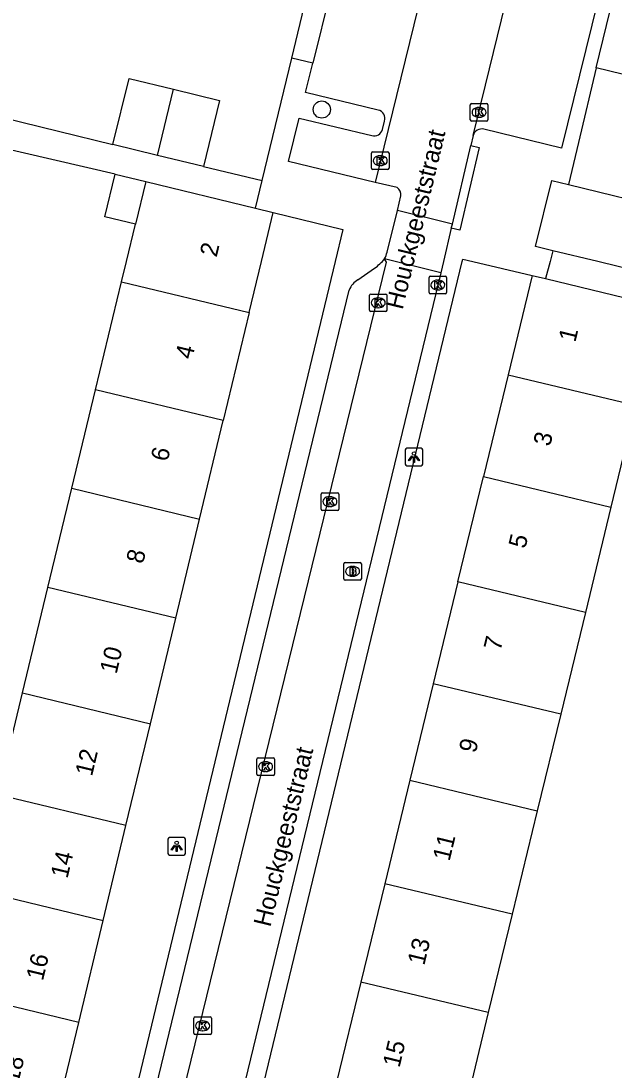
# Model space of a CAD drawing. Extents: x 162812 to 163818, y 381639 to 382470.
# Drawn here: x 163366.7 to 163400.4, y 382204.1 to 382263.7 of the extents above; entities that cross this region are included whole.
import ezdxf

# ---------------------------------------------------------------- set-up
doc = ezdxf.new("R2010")
doc.units = 0
for name, color, linetype in [('IMGEO_Boom', 7, 'Continuous'), ('IMGEO_Brandkraan', 7, 'Continuous'), ('IMGEO_Kolk', 7, 'Continuous'), ('IMGEO_Lichtpunt', 7, 'Continuous'), ('IMGEO_Muur', 7, 'Continuous'), ('IMGEO_Openbare_ruimte_label', 7, 'Continuous'), ('IMGEO_Pand', 7, 'Continuous'), ('IMGEO_Pand_nummerreeks', 7, 'Continuous'), ('IMGEO_Rijbaan_lokaal_open', 7, 'Continuous'), ('IMGEO_Voetpad_open', 7, 'Continuous')]:
    doc.layers.add(name, color=color, linetype=linetype)

msp = doc.modelspace()

# ---------------------------------------------------------------- linework, layer by layer
at = {"layer": 'IMGEO_Boom'}
msp.add_circle((163383.761, 382258.631), 0.489, dxfattribs=at)
at = {"layer": 'IMGEO_Brandkraan'}
for p, q in [((163385.08, 382232.913), (163385.932, 382232.913)), ((163385.005, 382231.987), (163385.005, 382232.839)), ((163385.493, 382232.693), (163385.518, 382232.693)), ((163386.006, 382232.839), (163386.006, 382231.987)), ((163385.932, 382231.913), (163385.08, 382231.913)), ((163385.516, 382232.133), (163385.491, 382232.133))]:
    msp.add_line(p, q, dxfattribs=at)
for points in [[(163385.08, 382232.913), (163385.932, 382232.913)], [(163385.005, 382231.987), (163385.005, 382232.839)], [(163385.353, 382232.613), (163385.353, 382232.213), (163385.566, 382232.213)], [(163385.584, 382232.613), (163385.353, 382232.613)], [(163385.532, 382232.532), (163385.478, 382232.532), (163385.478, 382232.456)], [(163385.478, 382232.456), (163385.531, 382232.456)], [(163385.54, 382232.38), (163385.478, 382232.38), (163385.478, 382232.299)], [(163385.478, 382232.299), (163385.54, 382232.299)], [(163386.006, 382232.839), (163386.006, 382231.987)], [(163385.932, 382231.913), (163385.08, 382231.913)]]:
    msp.add_lwpolyline(points, dxfattribs=at)
for centre, radius, start, end in [((163385.082, 382232.837), 0.0765, 91.55205, 178.44795), ((163385.082, 382232.837), 0.0765, 91.55205, 178.44795), ((163385.93, 382232.837), 0.0765, 1.55205, 88.44795), ((163385.93, 382232.837), 0.0765, 1.55205, 88.44795), ((163385.533, 382232.494), 0.0379, 267.82845, 90.93552), ((163385.541, 382232.339), 0.0404, 269.87594, 90.50774), ((163385.588, 382232.468), 0.145, 59.4692, 91.53667), ((163385.613, 382232.515), 0.0922, 285.51372, 58.15012), ((163385.618, 382232.323), 0.105, 301.31148, 78.98903), ((163385.082, 382231.989), 0.0765, 181.55205, 268.44795), ((163385.082, 382231.989), 0.0765, 181.55205, 268.44795), ((163385.572, 382232.464), 0.251, 268.66757, 293.53466), ((163385.93, 382231.989), 0.0765, 271.55205, 358.44795), ((163385.93, 382231.989), 0.0765, 271.55205, 358.44795)]:
    msp.add_arc(centre, radius, start, end, dxfattribs=at)
for centre, major_axis, ratio, start_param, end_param in [((163385.492, 382232.413), (-0.387, 0.002), 0.722429, 4.712389, 7.853982), ((163385.517, 382232.413), (-0.39, 0.002), 0.717154, 1.570796, 4.712389)]:
    msp.add_ellipse(centre, major_axis=major_axis, ratio=ratio, start_param=start_param, end_param=end_param, dxfattribs=at)
at = {"layer": 'IMGEO_Kolk'}
for p, q in [((163392.193, 382258.045), (163392.193, 382258.897)), ((163392.268, 382258.971), (163393.12, 382258.971)), ((163392.681, 382258.751), (163392.706, 382258.751)), ((163393.194, 382258.897), (163393.194, 382258.045)), ((163393.12, 382257.971), (163392.268, 382257.971)), ((163392.704, 382258.191), (163392.679, 382258.191)), ((163386.578, 382255.3), (163386.578, 382256.152)), ((163386.653, 382256.226), (163387.505, 382256.226)), ((163387.579, 382256.152), (163387.579, 382255.3)), ((163387.066, 382256.006), (163387.091, 382256.006)), ((163387.505, 382255.226), (163386.653, 382255.226)), ((163387.089, 382255.446), (163387.064, 382255.446)), ((163389.849, 382248.246), (163389.849, 382249.098)), ((163389.924, 382249.172), (163390.776, 382249.172)), ((163390.337, 382248.952), (163390.362, 382248.952)), ((163390.85, 382249.098), (163390.85, 382248.246)), ((163390.36, 382248.392), (163390.335, 382248.392)), ((163386.462, 382247.232), (163386.462, 382248.084)), ((163386.537, 382248.158), (163387.389, 382248.158)), ((163386.95, 382247.938), (163386.975, 382247.938)), ((163387.463, 382248.084), (163387.463, 382247.232)), ((163390.776, 382248.172), (163389.924, 382248.172)), ((163387.389, 382247.158), (163386.537, 382247.158)), ((163386.973, 382247.378), (163386.948, 382247.378)), ((163383.721, 382235.947), (163383.721, 382236.799)), ((163383.796, 382236.873), (163384.648, 382236.873)), ((163384.209, 382236.653), (163384.234, 382236.653)), ((163384.722, 382236.799), (163384.722, 382235.947)), ((163384.648, 382235.873), (163383.796, 382235.873)), ((163384.232, 382236.093), (163384.207, 382236.093)), ((163380.068, 382220.901), (163380.068, 382221.753)), ((163380.143, 382221.827), (163380.995, 382221.827)), ((163380.556, 382221.607), (163380.581, 382221.607)), ((163381.069, 382221.753), (163381.069, 382220.901)), ((163380.579, 382221.047), (163380.554, 382221.047)), ((163380.995, 382220.827), (163380.143, 382220.827)), ((163376.494, 382206.19), (163376.494, 382207.042)), ((163376.569, 382207.116), (163377.421, 382207.116)), ((163376.982, 382206.896), (163377.007, 382206.896)), ((163377.495, 382207.042), (163377.495, 382206.19)), ((163377.421, 382206.116), (163376.569, 382206.116)), ((163377.005, 382206.336), (163376.98, 382206.336))]:
    msp.add_line(p, q, dxfattribs=at)
for points in [[(163392.193, 382258.045), (163392.193, 382258.897)], [(163392.268, 382258.971), (163393.12, 382258.971)], [(163392.514, 382258.671), (163392.637, 382258.671), (163392.637, 382258.52), (163392.767, 382258.671), (163392.931, 382258.671), (163392.785, 382258.52), (163392.938, 382258.271), (163392.786, 382258.271), (163392.701, 382258.435), (163392.637, 382258.368), (163392.637, 382258.271), (163392.514, 382258.271), (163392.514, 382258.671)], [(163393.194, 382258.897), (163393.194, 382258.045)], [(163393.12, 382257.971), (163392.268, 382257.971)], [(163386.578, 382255.3), (163386.578, 382256.152)], [(163386.653, 382256.226), (163387.505, 382256.226)], [(163387.579, 382256.152), (163387.579, 382255.3)], [(163386.899, 382255.926), (163387.022, 382255.926), (163387.022, 382255.775), (163387.152, 382255.926), (163387.316, 382255.926), (163387.17, 382255.775), (163387.323, 382255.526), (163387.171, 382255.526), (163387.086, 382255.69), (163387.022, 382255.623), (163387.022, 382255.526), (163386.899, 382255.526), (163386.899, 382255.926)], [(163387.505, 382255.226), (163386.653, 382255.226)], [(163389.849, 382248.246), (163389.849, 382249.098)], [(163389.924, 382249.172), (163390.776, 382249.172)], [(163390.85, 382249.098), (163390.85, 382248.246)], [(163390.17, 382248.872), (163390.293, 382248.872), (163390.293, 382248.721), (163390.423, 382248.872), (163390.587, 382248.872), (163390.441, 382248.721), (163390.594, 382248.472), (163390.442, 382248.472), (163390.357, 382248.636), (163390.293, 382248.569), (163390.293, 382248.472), (163390.17, 382248.472), (163390.17, 382248.872)], [(163386.462, 382247.232), (163386.462, 382248.084)], [(163386.537, 382248.158), (163387.389, 382248.158)], [(163386.783, 382247.858), (163386.906, 382247.858), (163386.906, 382247.707), (163387.036, 382247.858), (163387.2, 382247.858), (163387.054, 382247.707), (163387.207, 382247.458), (163387.055, 382247.458), (163386.97, 382247.622), (163386.906, 382247.555), (163386.906, 382247.458), (163386.783, 382247.458), (163386.783, 382247.858)], [(163387.463, 382248.084), (163387.463, 382247.232)], [(163390.776, 382248.172), (163389.924, 382248.172)], [(163387.389, 382247.158), (163386.537, 382247.158)], [(163383.721, 382235.947), (163383.721, 382236.799)], [(163383.796, 382236.873), (163384.648, 382236.873)], [(163384.042, 382236.573), (163384.165, 382236.573), (163384.165, 382236.422), (163384.295, 382236.573), (163384.459, 382236.573), (163384.313, 382236.422), (163384.466, 382236.173), (163384.314, 382236.173), (163384.229, 382236.337), (163384.165, 382236.27), (163384.165, 382236.173), (163384.042, 382236.173), (163384.042, 382236.573)], [(163384.722, 382236.799), (163384.722, 382235.947)], [(163384.648, 382235.873), (163383.796, 382235.873)], [(163380.068, 382220.901), (163380.068, 382221.753)], [(163380.143, 382221.827), (163380.995, 382221.827)], [(163381.069, 382221.753), (163381.069, 382220.901)], [(163380.389, 382221.527), (163380.512, 382221.527), (163380.512, 382221.376), (163380.642, 382221.527), (163380.806, 382221.527), (163380.66, 382221.376), (163380.813, 382221.127), (163380.661, 382221.127), (163380.576, 382221.291), (163380.512, 382221.224), (163380.512, 382221.127), (163380.389, 382221.127), (163380.389, 382221.527)], [(163380.995, 382220.827), (163380.143, 382220.827)], [(163376.494, 382206.19), (163376.494, 382207.042)], [(163376.569, 382207.116), (163377.421, 382207.116)], [(163376.815, 382206.816), (163376.938, 382206.816), (163376.938, 382206.665), (163377.068, 382206.816), (163377.232, 382206.816), (163377.086, 382206.665), (163377.239, 382206.416), (163377.087, 382206.416), (163377.002, 382206.58), (163376.938, 382206.513), (163376.938, 382206.416), (163376.815, 382206.416), (163376.815, 382206.816)], [(163377.495, 382207.042), (163377.495, 382206.19)], [(163377.421, 382206.116), (163376.569, 382206.116)]]:
    msp.add_lwpolyline(points, dxfattribs=at)
for centre, start, end in [((163392.27, 382258.895), 91.55205, 178.44795), ((163392.27, 382258.895), 91.55205, 178.44795), ((163393.118, 382258.895), 1.55205, 88.44795), ((163393.118, 382258.895), 1.55205, 88.44795), ((163392.27, 382258.047), 181.55205, 268.44795), ((163392.27, 382258.047), 181.55205, 268.44795), ((163393.118, 382258.047), 271.55205, 358.44795), ((163393.118, 382258.047), 271.55205, 358.44795), ((163386.655, 382256.15), 91.55205, 178.44795), ((163386.655, 382256.15), 91.55205, 178.44795), ((163387.503, 382256.15), 1.55205, 88.44795), ((163387.503, 382256.15), 1.55205, 88.44795), ((163386.655, 382255.302), 181.55205, 268.44795), ((163386.655, 382255.302), 181.55205, 268.44795), ((163387.503, 382255.302), 271.55205, 358.44795), ((163387.503, 382255.302), 271.55205, 358.44795), ((163389.926, 382249.096), 91.55205, 178.44795), ((163389.926, 382249.096), 91.55205, 178.44795), ((163390.774, 382249.096), 1.55205, 88.44795), ((163390.774, 382249.096), 1.55205, 88.44795), ((163386.539, 382248.082), 91.55205, 178.44795), ((163386.539, 382248.082), 91.55205, 178.44795), ((163387.387, 382248.082), 1.55205, 88.44795), ((163387.387, 382248.082), 1.55205, 88.44795), ((163389.926, 382248.248), 181.55205, 268.44795), ((163389.926, 382248.248), 181.55205, 268.44795), ((163390.774, 382248.248), 271.55205, 358.44795), ((163390.774, 382248.248), 271.55205, 358.44795), ((163386.539, 382247.234), 181.55205, 268.44795), ((163386.539, 382247.234), 181.55205, 268.44795), ((163387.387, 382247.234), 271.55205, 358.44795), ((163387.387, 382247.234), 271.55205, 358.44795), ((163383.798, 382236.797), 91.55205, 178.44795), ((163383.798, 382236.797), 91.55205, 178.44795), ((163384.646, 382236.797), 1.55205, 88.44795), ((163384.646, 382236.797), 1.55205, 88.44795), ((163383.798, 382235.949), 181.55205, 268.44795), ((163383.798, 382235.949), 181.55205, 268.44795), ((163384.646, 382235.949), 271.55205, 358.44795), ((163384.646, 382235.949), 271.55205, 358.44795), ((163380.145, 382221.751), 91.55205, 178.44795), ((163380.145, 382221.751), 91.55205, 178.44795), ((163380.993, 382221.751), 1.55205, 88.44795), ((163380.993, 382221.751), 1.55205, 88.44795), ((163380.145, 382220.903), 181.55205, 268.44795), ((163380.145, 382220.903), 181.55205, 268.44795), ((163380.993, 382220.903), 271.55205, 358.44795), ((163380.993, 382220.903), 271.55205, 358.44795), ((163376.571, 382207.04), 91.55205, 178.44795), ((163376.571, 382207.04), 91.55205, 178.44795), ((163377.419, 382207.04), 1.55205, 88.44795), ((163377.419, 382207.04), 1.55205, 88.44795), ((163376.571, 382206.192), 181.55205, 268.44795), ((163376.571, 382206.192), 181.55205, 268.44795), ((163377.419, 382206.192), 271.55205, 358.44795), ((163377.419, 382206.192), 271.55205, 358.44795)]:
    msp.add_arc(centre, 0.0765, start, end, dxfattribs=at)
for centre, major_axis, ratio, start_param, end_param in [((163392.68, 382258.471), (-0.387, 0.002), 0.722429, 4.712389, 7.853982), ((163392.705, 382258.471), (-0.39, 0.002), 0.717154, 1.570796, 4.712389), ((163387.065, 382255.726), (-0.387, 0.002), 0.722429, 4.712389, 7.853982), ((163387.09, 382255.726), (-0.39, 0.002), 0.717154, 1.570796, 4.712389), ((163390.336, 382248.672), (-0.387, 0.002), 0.722429, 4.712389, 7.853982), ((163390.361, 382248.672), (-0.39, 0.002), 0.717154, 1.570796, 4.712389), ((163386.949, 382247.658), (-0.387, 0.002), 0.722429, 4.712389, 7.853982), ((163386.974, 382247.658), (-0.39, 0.002), 0.717154, 1.570796, 4.712389), ((163384.208, 382236.373), (-0.387, 0.002), 0.722429, 4.712389, 7.853982), ((163384.233, 382236.373), (-0.39, 0.002), 0.717154, 1.570796, 4.712389), ((163380.555, 382221.327), (-0.387, 0.002), 0.722429, 4.712389, 7.853982), ((163380.58, 382221.327), (-0.39, 0.002), 0.717154, 1.570796, 4.712389), ((163376.981, 382206.616), (-0.387, 0.002), 0.722429, 4.712389, 7.853982), ((163377.006, 382206.616), (-0.39, 0.002), 0.717154, 1.570796, 4.712389)]:
    msp.add_ellipse(centre, major_axis=major_axis, ratio=ratio, start_param=start_param, end_param=end_param, dxfattribs=at)
at = {"layer": 'IMGEO_Lichtpunt'}
for p, q in [((163388.499, 382239.307), (163388.499, 382238.5)), ((163388.499, 382239.307), (163388.499, 382238.5)), ((163389.401, 382239.402), (163388.593, 382239.402)), ((163389.401, 382239.402), (163388.593, 382239.402)), ((163389.495, 382238.5), (163389.495, 382239.307)), ((163389.495, 382238.5), (163389.495, 382239.307)), ((163388.593, 382238.406), (163389.401, 382238.406)), ((163388.593, 382238.406), (163389.401, 382238.406)), ((163375.024, 382217.208), (163375.024, 382216.401)), ((163375.024, 382217.208), (163375.024, 382216.401)), ((163375.926, 382217.303), (163375.118, 382217.303)), ((163375.926, 382217.303), (163375.118, 382217.303)), ((163376.02, 382216.401), (163376.02, 382217.208)), ((163376.02, 382216.401), (163376.02, 382217.208)), ((163375.118, 382216.307), (163375.926, 382216.307)), ((163375.118, 382216.307), (163375.926, 382216.307))]:
    msp.add_line(p, q, dxfattribs=at)
for points in [[(163388.873, 382238.971), (163388.912, 382238.943), (163388.724, 382238.681), (163388.686, 382238.708), (163388.873, 382238.971)], [(163388.975, 382238.923), (163389.022, 382238.923), (163389.022, 382238.601), (163388.975, 382238.601), (163388.975, 382238.923)], [(163389.085, 382238.943), (163389.123, 382238.97), (163389.31, 382238.708), (163389.271, 382238.68), (163389.085, 382238.943)], [(163375.398, 382216.872), (163375.437, 382216.844), (163375.249, 382216.582), (163375.211, 382216.609), (163375.398, 382216.872)], [(163375.5, 382216.824), (163375.547, 382216.824), (163375.547, 382216.502), (163375.5, 382216.502), (163375.5, 382216.824)], [(163375.61, 382216.844), (163375.648, 382216.871), (163375.835, 382216.609), (163375.796, 382216.581), (163375.61, 382216.844)]]:
    msp.add_lwpolyline(points, dxfattribs=at)
for centre in [(163388.998, 382239.105), (163375.523, 382217.006)]:
    msp.add_circle(centre, 0.0994, dxfattribs=at)
for centre, start, end in [((163388.593, 382239.307), 90, 180), ((163388.593, 382239.307), 90, 180), ((163389.401, 382239.307), 0, 90), ((163389.401, 382239.307), 0, 90), ((163388.593, 382238.5), 180, 270), ((163388.593, 382238.5), 180, 270), ((163389.401, 382238.5), 270, 0), ((163389.401, 382238.5), 270, 360), ((163375.118, 382217.208), 90, 180), ((163375.118, 382217.208), 90, 180), ((163375.926, 382217.208), 0, 90), ((163375.926, 382217.208), 0, 90), ((163375.118, 382216.401), 180, 270), ((163375.118, 382216.401), 180, 270), ((163375.926, 382216.401), 270, 0), ((163375.926, 382216.401), 270, 360)]:
    msp.add_arc(centre, 0.0946, start, end, dxfattribs=at)
at = {"layer": 'IMGEO_Muur'}
msp.add_lwpolyline([(163399.348, 382260.994), (163398.334, 382256.764)], dxfattribs=at)
at = {"layer": 'IMGEO_Pand'}
for points in [[(163399.348, 382260.994), (163401.1, 382268.221)], [(163405.397, 382259.528), (163399.348, 382260.994)], [(163371.902, 382256.645), (163372.816, 382260.396), (163375.347, 382259.78)], [(163374.433, 382256.028), (163375.347, 382259.78)], [(163375.347, 382259.78), (163377.948, 382259.146), (163377.037, 382255.394)], [(163374.433, 382256.028), (163371.902, 382256.645)], [(163377.037, 382255.394), (163374.433, 382256.028)], [(163373.174, 382252.114), (163371.433, 382252.534), (163372.02, 382254.963)], [(163372.02, 382254.963), (163373.76, 382254.543)], [(163373.76, 382254.543), (163373.174, 382252.114)], [(163373.76, 382254.543), (163379.995, 382253.037)], [(163396.888, 382250.618), (163395.905, 382250.856), (163396.814, 382254.605), (163397.761, 382254.375)], [(163397.761, 382254.375), (163403.656, 382252.946)], [(163379.634, 382247.109), (163380.328, 382250), (163380.999, 382252.795)], [(163379.995, 382253.037), (163380.999, 382252.795)], [(163372.388, 382248.857), (163372.664, 382250), (163373.174, 382252.114)], [(163402.746, 382249.198), (163399.436, 382250), (163396.888, 382250.618)], [(163395.709, 382249.214), (163394.342, 382243.576)], [(163395.709, 382249.214), (163396.461, 382249.032)], [(163396.461, 382249.032), (163402.94, 382247.461)], [(163370.91, 382242.725), (163372.388, 382248.857)], [(163372.388, 382248.857), (163379.634, 382247.109)], [(163379.634, 382247.109), (163378.161, 382240.975)], [(163394.342, 382243.576), (163392.94, 382237.792)], [(163394.342, 382243.576), (163401.579, 382241.847)], [(163369.562, 382237.136), (163370.91, 382242.725)], [(163378.161, 382240.975), (163370.91, 382242.725)], [(163401.579, 382241.847), (163400.177, 382236.064)], [(163376.819, 382235.386), (163378.161, 382240.975)], [(163391.49, 382231.814), (163392.94, 382237.792)], [(163392.94, 382237.792), (163400.177, 382236.064)], [(163368.203, 382231.502), (163369.562, 382237.136)], [(163369.562, 382237.136), (163376.819, 382235.386)], [(163400.177, 382236.064), (163398.727, 382230.085)], [(163375.465, 382229.749), (163376.819, 382235.386)], [(163391.49, 382231.814), (163390.089, 382226.035)], [(163398.727, 382230.085), (163391.49, 382231.814)], [(163366.761, 382225.519), (163368.203, 382231.502)], [(163375.465, 382229.749), (163368.203, 382231.502)], [(163398.727, 382230.085), (163397.326, 382224.306)], [(163374.028, 382223.766), (163375.465, 382229.749)], [(163390.089, 382226.035), (163388.76, 382220.554)], [(163397.326, 382224.306), (163390.089, 382226.035)], [(163365.365, 382219.733), (163366.761, 382225.519)], [(163366.761, 382225.519), (163374.028, 382223.766)], [(163397.326, 382224.306), (163395.997, 382218.826)], [(163372.639, 382217.978), (163374.028, 382223.766)], [(163388.76, 382220.554), (163387.335, 382214.676)], [(163388.76, 382220.554), (163395.997, 382218.826)], [(163372.639, 382217.978), (163365.365, 382219.733)], [(163395.997, 382218.826), (163394.571, 382212.947)], [(163371.345, 382212.591), (163372.639, 382217.978)], [(163387.335, 382214.676), (163385.98, 382209.091)], [(163394.571, 382212.947), (163387.335, 382214.676)], [(163364.067, 382214.346), (163371.345, 382212.591)], [(163394.571, 382212.947), (163393.217, 382207.362)], [(163369.955, 382206.804), (163371.345, 382212.591)], [(163385.98, 382209.091), (163384.602, 382203.408)], [(163393.217, 382207.362), (163385.98, 382209.091)], [(163369.955, 382206.804), (163362.672, 382208.562)], [(163393.217, 382207.362), (163391.839, 382201.679)], [(163368.543, 382200.923), (163369.955, 382206.804)]]:
    msp.add_lwpolyline(points, dxfattribs=at)
at = {"layer": 'IMGEO_Rijbaan_lokaal_open'}
for points in [[(163391.174, 382272.417), (163386.793, 382254.498)], [(163392.351, 382257.15), (163395.824, 382271.309)], [(163392.351, 382257.15), (163392.217, 382256.592)], [(163391.176, 382252.13), (163392.217, 382256.592)], [(163388.036, 382254.205), (163386.793, 382254.498)], [(163388.05, 382252.902), (163388.251, 382253.738)], [(163387.468, 382250.534), (163388.05, 382252.902)], [(163391.176, 382252.13), (163388.05, 382252.902)], [(163391.112, 382251.891), (163391.176, 382252.13)], [(163391.112, 382251.891), (163390.667, 382250), (163390.517, 382249.365)], [(163373.018, 382191.062), (163387.426, 382249.958), (163387.327, 382250.156)], [(163390.517, 382249.365), (163387.327, 382250.156)], [(163390.517, 382249.365), (163376.21, 382190.29)]]:
    msp.add_lwpolyline(points, dxfattribs=at)
for centre, radius, start, end in [((163387.742, 382253.787), 0.511, 354.51278, 54.92853), ((163385.844, 382250.924), 1.67, 332.60598, 346.48139)]:
    msp.add_arc(centre, radius, start, end, dxfattribs=at)
at = {"layer": 'IMGEO_Voetpad_open'}
for points in [[(163395.671, 382267.2), (163399.773, 382266.205), (163397.366, 382256.432), (163392.97, 382257.511)], [(163384.25, 382265.324), (163383.257, 382261.265)], [(163382.062, 382261.539), (163382.868, 382264.95)], [(163380.374, 382254.594), (163382.062, 382261.539)], [(163383.257, 382261.265), (163382.062, 382261.539)], [(163386.961, 382258.604), (163382.844, 382259.592), (163383.257, 382261.265)], [(163399.348, 382260.994), (163398.334, 382256.764), (163397.761, 382254.375)], [(163365.731, 382258.157), (163371.902, 382256.645)], [(163386.793, 382254.498), (163381.869, 382255.68), (163382.482, 382258.137), (163386.598, 382257.148)], [(163387.201, 382257.505), (163387.318, 382257.978)], [(163372.02, 382254.963), (163363.258, 382256.98), (163362.432, 382253.792)], [(163392.217, 382256.592), (163392.703, 382256.478), (163391.598, 382251.777), (163391.112, 382251.891)], [(163377.037, 382255.394), (163380.374, 382254.594)], [(163379.995, 382253.037), (163380.374, 382254.594)], [(163380.999, 382252.795), (163384.952, 382251.829), (163384.512, 382250), (163370.239, 382190.68)], [(163377.154, 382189.643), (163391.74, 382250), (163391.771, 382250.13), (163392.33, 382250), (163395.709, 382249.214)], [(163396.888, 382250.618), (163396.722, 382250), (163396.461, 382249.032)], [(163385.806, 382248.971), (163386.762, 382249.625)], [(163372.136, 382194.003), (163385.312, 382248.385)]]:
    msp.add_lwpolyline(points, dxfattribs=at)
for centre, radius, start, end in [((163386.857, 382258.13), 0.485, 341.72468, 77.66647), ((163386.732, 382257.609), 0.48, 253.78432, 347.47012), ((163392.838, 382257.025), 0.503, 74.8435, 165.65787), ((163384.988, 382252.079), 3.028, 305.86652, 320.57978), ((163386.49, 382247.893), 1.276, 122.39385, 157.34414)]:
    msp.add_arc(centre, radius, start, end, dxfattribs=at)

# ---------------------------------------------------------------- texts
at = {"layer": 'IMGEO_Openbare_ruimte_label'}
for p in [(163388.347, 382247.229), (163380.841, 382212.184)]:
    msp.add_text('Houckgeeststraat', height=1, rotation=76.40844, dxfattribs=at).set_placement(p)
at = {"layer": 'IMGEO_Pand_nummerreeks'}
for s, rotation, p in [('2', 76.49748, (163377.786, 382250.211)), ('1', 76.37039, (163398.155, 382245.382)), ('4', 76.49748, (163376.393, 382244.408)), ('3', 76.37039, (163396.721, 382239.468)), ('6', 76.49748, (163375, 382238.604)), ('5', 76.37039, (163395.314, 382233.665)), ('8', 76.49748, (163373.607, 382232.803)), ('7', 76.37039, (163393.907, 382227.862)), ('10', 76.49748, (163372.105, 382226.551)), ('9', 76.37039, (163392.499, 382222.059)), ('12', 76.49748, (163370.71, 382220.74)), ('11', 76.37039, (163391.011, 382215.92)), ('14', 76.49748, (163369.316, 382214.939)), ('13', 76.37039, (163389.577, 382210.007)), ('16', 76.49748, (163367.923, 382209.134)), ('15', 76.37039, (163388.17, 382204.203)), ('18', 76.4956, (163366.531, 382203.332))]:
    msp.add_text(s, height=1, rotation=rotation, dxfattribs=at).set_placement(p)

doc.saveas('drawing.dxf')
